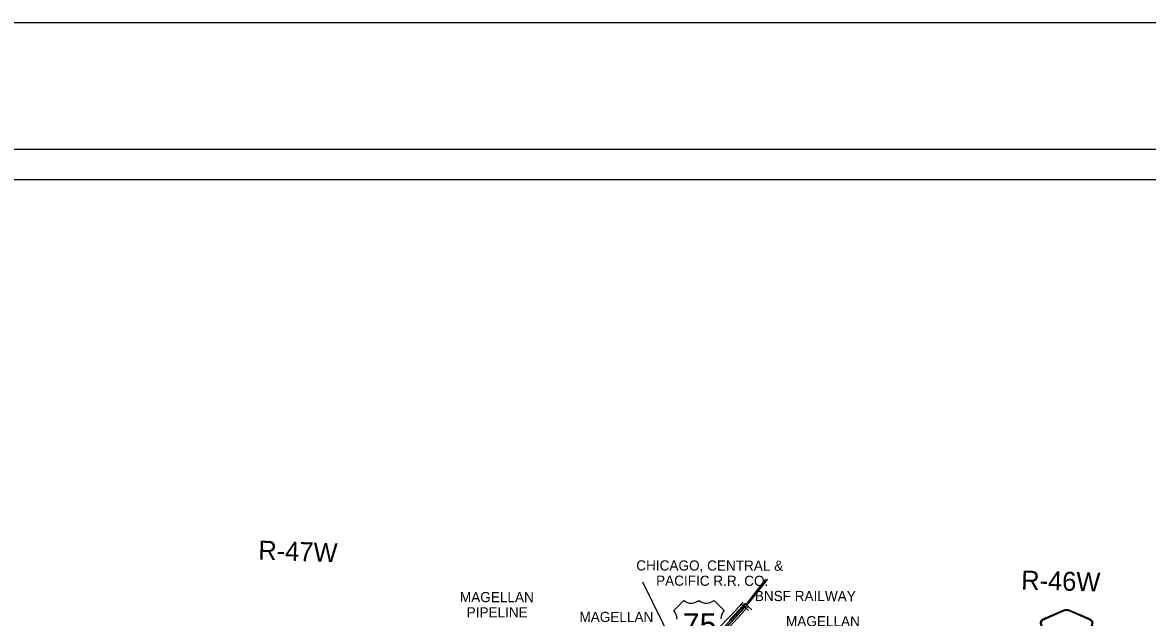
# Model space of a CAD drawing. Extents: x -157.2 to -99.3, y 12.2 to 46.2.
# Drawn here: x -149.64 to -140.76, y 41.47 to 46.16 of the extents above; entities that cross this region are included whole.
import ezdxf

# ---------------------------------------------------------------- set-up
doc = ezdxf.new("R2010")
doc.units = 0
for name, color, linetype in [('tdCoFrame', 7, 'Continuous'), ('tdCoPipe', 7, 'Continuous'), ('tdCoPipeTxt', 7, 'Continuous'), ('tdCoPlotFrame', 7, 'Continuous'), ('tdCoRRCL', 7, 'Continuous'), ('tdCoRROwnerTxt', 7, 'Continuous'), ('tdCoShieldCoRte', 7, 'Continuous'), ('tdCoShieldUsRte', 7, 'Continuous'), ('tdCoTwpRngTxt', 7, 'Continuous')]:
    doc.layers.add(name, color=color, linetype=linetype)

msp = doc.modelspace()

# ---------------------------------------------------------------- linework, layer by layer
at = {"layer": 'tdCoFrame'}
for points in [[(-155.7179, 45.1623), (-102.2179, 45.1623), (-102.2179, 13.1623), (-155.7179, 13.1623)], [(-155.4779, 44.9223), (-102.4579, 44.9223), (-102.4579, 13.4023), (-155.4779, 13.4023)]]:
    msp.add_lwpolyline(points, close=True, dxfattribs=at)
at = {"layer": 'tdCoPipe'}
msp.add_lwpolyline([(-144.5162, 38.9524), (-144.2247, 39.1641), (-144.1886, 40.6186), (-144.7421, 41.7477)], dxfattribs=at)
at = {"layer": 'tdCoPlotFrame'}
msp.add_lwpolyline([(-157.2179, 46.1623), (-101.2179, 46.1623), (-101.2179, 12.1623), (-157.2179, 12.1623)], close=True, dxfattribs=at)
at = {"layer": 'tdCoRRCL'}
for p, q in [((-143.9094, 41.5234), (-143.9652, 41.5735)), ((-143.9388, 41.5785), (-143.8822, 41.5293))]:
    msp.add_line(p, q, dxfattribs=at)
for points in [[(-145.342, 40.1057), (-145.3067, 40.1402), (-145.2029, 40.2269), (-144.9721, 40.4538), (-144.7871, 40.6517), (-144.2071, 41.2578), (-143.9055, 41.5802), (-143.7559, 41.7703)], [(-145.3383, 40.1415), (-145.2775, 40.186), (-145.1657, 40.2892), (-145.02, 40.4365), (-143.9066, 41.5975), (-143.8071, 41.7262)], [(-143.8071, 41.7262), (-143.7874, 41.7492), (-143.7728, 41.7708)], [(-143.9526, 41.5882), (-143.9784, 41.5595), (-144.0204, 41.5142), (-144.0468, 41.4869), (-144.1501, 41.3789)], [(-144.1107, 41.3662), (-143.9378, 41.5484)], [(-143.9107, 41.5536), (-144.0814, 41.3683)], [(-143.9391, 41.5783), (-143.962, 41.5519), (-144.0133, 41.4945), (-144.0585, 41.4477)]]:
    msp.add_lwpolyline(points, dxfattribs=at)
at = {"layer": 'tdCoShieldCoRte'}
for points in [[(-141.5193, 41.1212), (-141.6013, 41.4041), (-141.6051, 41.4173), (-141.6059, 41.4232), (-141.6059, 41.431), (-141.6016, 41.4413), (-141.5944, 41.4498), (-141.5848, 41.4564), (-141.4175, 41.5288), (-141.41, 41.5304), (-141.3996, 41.5313), (-141.3891, 41.5304), (-141.3816, 41.5288), (-141.2143, 41.4564), (-141.2048, 41.4498), (-141.1975, 41.4413), (-141.1933, 41.431), (-141.1933, 41.4232), (-141.194, 41.4173), (-141.1979, 41.4041), (-141.2798, 41.1212)], [(-141.5135, 41.1276), (-141.5932, 41.4028), (-141.5969, 41.4155), (-141.5976, 41.4211), (-141.5976, 41.4286), (-141.5935, 41.4385), (-141.5866, 41.4467), (-141.5774, 41.4531), (-141.4168, 41.5225), (-141.4096, 41.5241), (-141.3996, 41.525), (-141.3896, 41.5241), (-141.3823, 41.5225), (-141.2218, 41.4531), (-141.2126, 41.4467), (-141.2056, 41.4385), (-141.2015, 41.4286), (-141.2015, 41.4211), (-141.2022, 41.4155), (-141.2059, 41.4028), (-141.2857, 41.1276)]]:
    msp.add_lwpolyline(points, close=True, dxfattribs=at)
at = {"layer": 'tdCoShieldUsRte'}
msp.add_lwpolyline([(-144.4729, 41.4545), (-144.4746, 41.4728), (-144.4794, 41.4906), (-144.4871, 41.5073), (-144.499, 41.5244), (-144.4201, 41.6032), (-144.4063, 41.5935), (-144.391, 41.5864), (-144.3746, 41.5823), (-144.3577, 41.5812), (-144.341, 41.5832), (-144.3248, 41.5882), (-144.3098, 41.596), (-144.3001, 41.6032), (-144.2863, 41.5935), (-144.271, 41.5864), (-144.2546, 41.5823), (-144.2377, 41.5812), (-144.2209, 41.5832), (-144.2048, 41.5882), (-144.1898, 41.596), (-144.1801, 41.6032), (-144.1013, 41.5244), (-144.112, 41.5094), (-144.12, 41.4929), (-144.1252, 41.4752), (-144.1274, 41.4569)], dxfattribs=at)

# ---------------------------------------------------------------- texts
at = {"layer": 'tdCoPipeTxt'}
for s, rotation, p in [('MAGELLAN', 359.88961, (-146.1854, 41.5893)), ('PIPELINE', 359.88961, (-146.1322, 41.4692)), ('MAGELLAN', 359.88961, (-145.2425, 41.4329)), ('MAGELLAN', 359.89066, (-143.6133, 41.3992))]:
    msp.add_text(s, height=0.08, rotation=rotation, dxfattribs=at).set_placement(p)
at = {"layer": 'tdCoRROwnerTxt'}
for s, rotation, p in [('CHICAGO, CENTRAL &', 359.89005, (-144.7942, 41.8391)), ('PACIFIC R.R. CO.', 359.89005, (-144.638, 41.7188)), ('BNSF RAILWAY', 359.89039, (-143.8591, 41.598))]:
    msp.add_text(s, height=0.08, rotation=rotation, dxfattribs=at).set_placement(p)
at = {"layer": 'tdCoShieldUsRte'}
msp.add_text('75', height=0.18, dxfattribs=at).set_placement((-144.4285, 41.3219))
at = {"layer": 'tdCoTwpRngTxt'}
for s, rotation, p in [('R-47W', 357.9996, (-147.7777, 41.9251)), ('R-46W', 358.4538, (-141.7592, 41.689))]:
    msp.add_text(s, height=0.15, rotation=rotation, dxfattribs=at).set_placement(p)

doc.saveas('drawing.dxf')
